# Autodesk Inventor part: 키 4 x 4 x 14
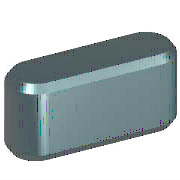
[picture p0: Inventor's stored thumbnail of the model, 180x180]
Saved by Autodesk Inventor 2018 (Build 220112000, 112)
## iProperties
IsCustomPart: 1
Created: 2012-02
Part Number: 키 4 x 4 x 14
Material: 강철, 연강
Description: 키 및 해당 키홈
Document SubType Name: Modeling
Standard: KS B 1311
Designer: mduedu
Standards Organization: KS
Language: ko-KR
Size Designation: 4 x 4 x 12
Categories: <MemberInstance><Categories><Category DisplayName="샤프트 부품" InternalName="7f7aeb1f-a693-4053-b835-cee3144e0d98" Mnemonic="SHFT"><Category DisplayName="키" Interna
Density: 1 g/cm^3
Appearance: 노란색
Author: mduedu
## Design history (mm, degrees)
workplane "Work Plane1"
workplane "Work Plane2"
sketch "스케치1"
  geometry: L1 (2, 2)-(12, 2); L2 (12, -2)-(2, -2); L3 (0, 8.8)-(0, -3.8) reference; L4 (-2.4, 0)-(14.4, 0) reference; L5 (14, 0)-(14, 7); A1 r 2 centre (2, 0) between (2, 2) and (2, -2); A2 r 2 centre (12, 0) between (12, -2) and (12, 2)
  constraints: 6 end point, 5 point on circle, 4 tangent, 3 point on line, 2 centre point, 1 horizontal, 1 parallel, 1 perpendicular
  dimensions: "d0" = 2 radius of A1 (= 0.5 x PB); "d13" = 2 radius of A2 (= 0.5 x PB); "d14" = 14 distance between parallel lines of L5 L3 (= NLG)
extrude "본체1" new body sketch "스케치1" taper "d3" = 0 deg; stored distance "d4" = 10
workplane "Work Plane3"
body "Solid1"
chamfer "모따기1" distance "d8" = 0.25 (= PHH); stored, may be unused: second distance "d9" = 0.25 (= PHH), angle "d15" = 45 deg
other parameters: "d1" = -2.5 (= -PNT), "d2" = 1.5 (= PH - PNT), "NLG" = 14 [user parameter; used in 3 equation terms], "PB" = 4 [user parameter; used in 2 equation terms], "PNT" = 2.5 [user parameter; used in 2 equation terms], "PH" = 4 [user parameter; used in 1 equation term], "PHH" = 0.25 [user parameter; used in 2 equation terms], "d10" = 0, "d16" = 0, "d17" = 0, "d18" = 0, "PLB2" = 14 (= NLG) [user parameter], "WDMAX" = 12 [user parameter], "PLB1" = 14 (= NLG) [user parameter], "RR" = 0.08 [user parameter], "PUEB" = 1.8 [user parameter]
